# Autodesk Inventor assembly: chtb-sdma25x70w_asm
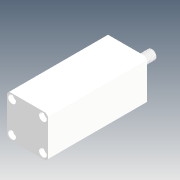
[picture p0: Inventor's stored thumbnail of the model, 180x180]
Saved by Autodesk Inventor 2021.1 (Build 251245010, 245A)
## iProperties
Company: Microsoft
Created: 2018-05
Part Number: chtb-sdma25x70w_asm
Description: STEP AP214
Document SubType Name: Assembly
Designer: user
Title: chtb-sdma25x70w_asm.STEP
Author: Windows
Revision Number: ÈÎºÎ
Sending System: SolidWorks 2015
Preprocessor: SwSTEP 2.0
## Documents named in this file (4)
- D:\Vault_2016\Projekty\Clamptek\Hydraulic\CHTB\CHTB-25\Inventor\chtb-sdma25x70w\chtb-sdma25x70w_asm.iam
- D:\Vault_2016\Projekty\Clamptek\Hydraulic\CHTB\CHTB-25\Inventor\chtb-sdma25x70w\CHTB-25QG.ipt
- D:\Vault_2016\Projekty\Clamptek\Hydraulic\CHTB\CHTB-25\Inventor\chtb-sdma25x70w\CHTB-SDMA25X70NBT.ipt
- D:\Vault_2016\Projekty\Clamptek\Hydraulic\CHTB\CHTB-25\Inventor\chtb-sdma25x70w\CHTB-SDMA25X70WHSG.ipt
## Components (3 placed, 3 different names)
1. CHTB-25QG_1
2. CHTB-SDMA25X70NBT_2
3. CHTB-SDMA25X70WHSG_3
